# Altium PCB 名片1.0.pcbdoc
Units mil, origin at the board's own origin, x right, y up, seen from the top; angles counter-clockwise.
Board outline 3543.3 x 1925.99 mil, 2 copper layers (Top Layer, Bottom Layer); 29 components, 32 nets, 159 pads, 0 vias.
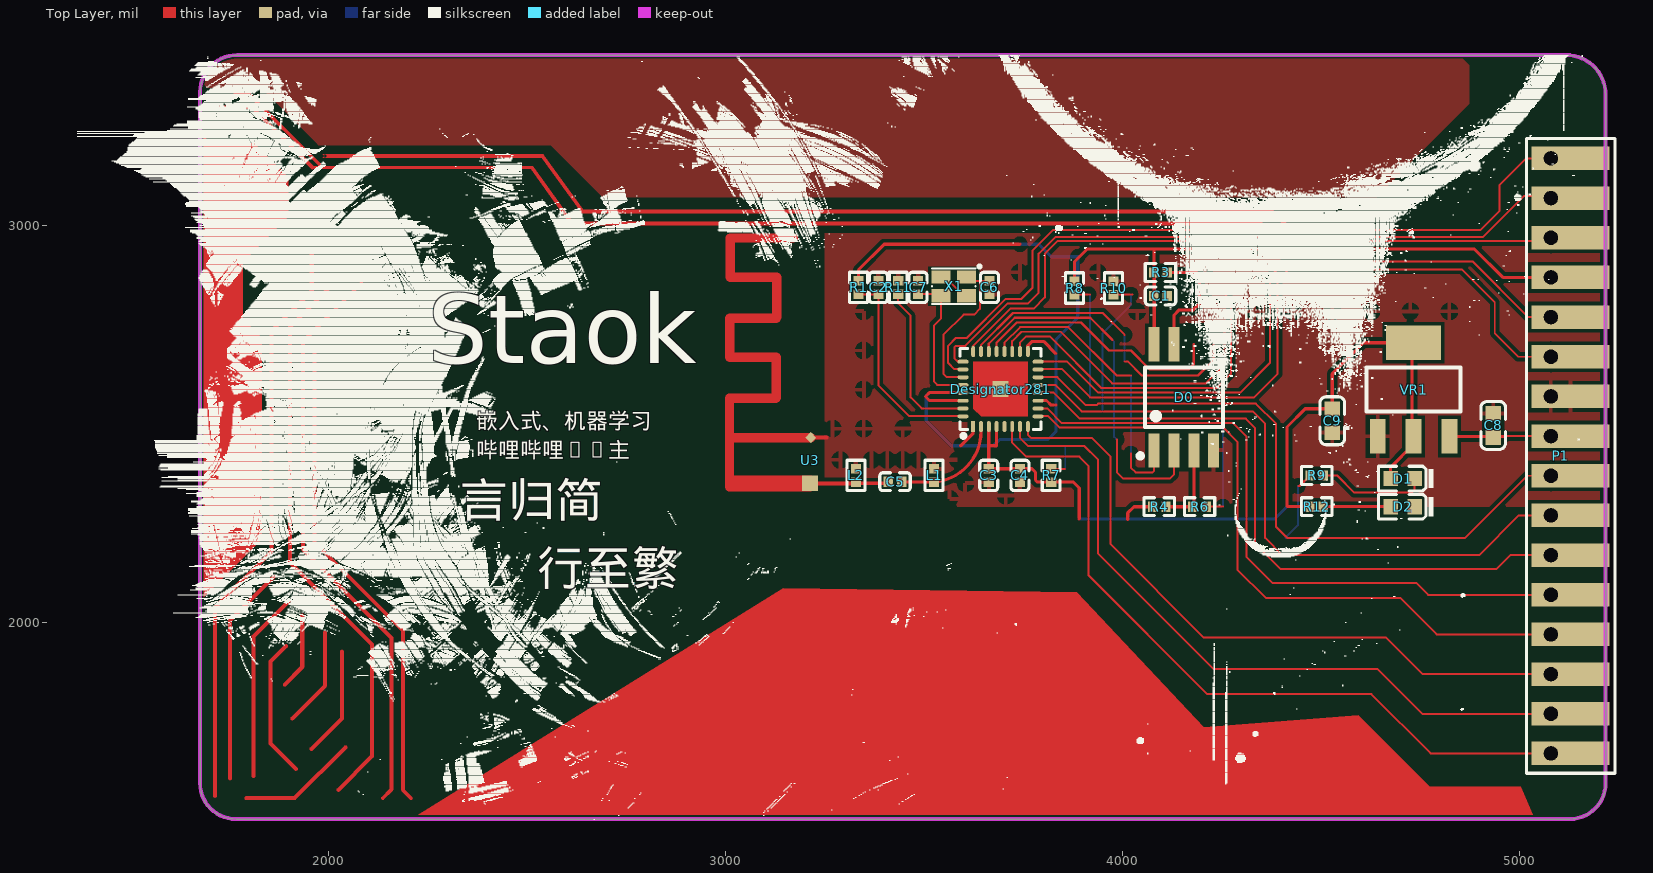
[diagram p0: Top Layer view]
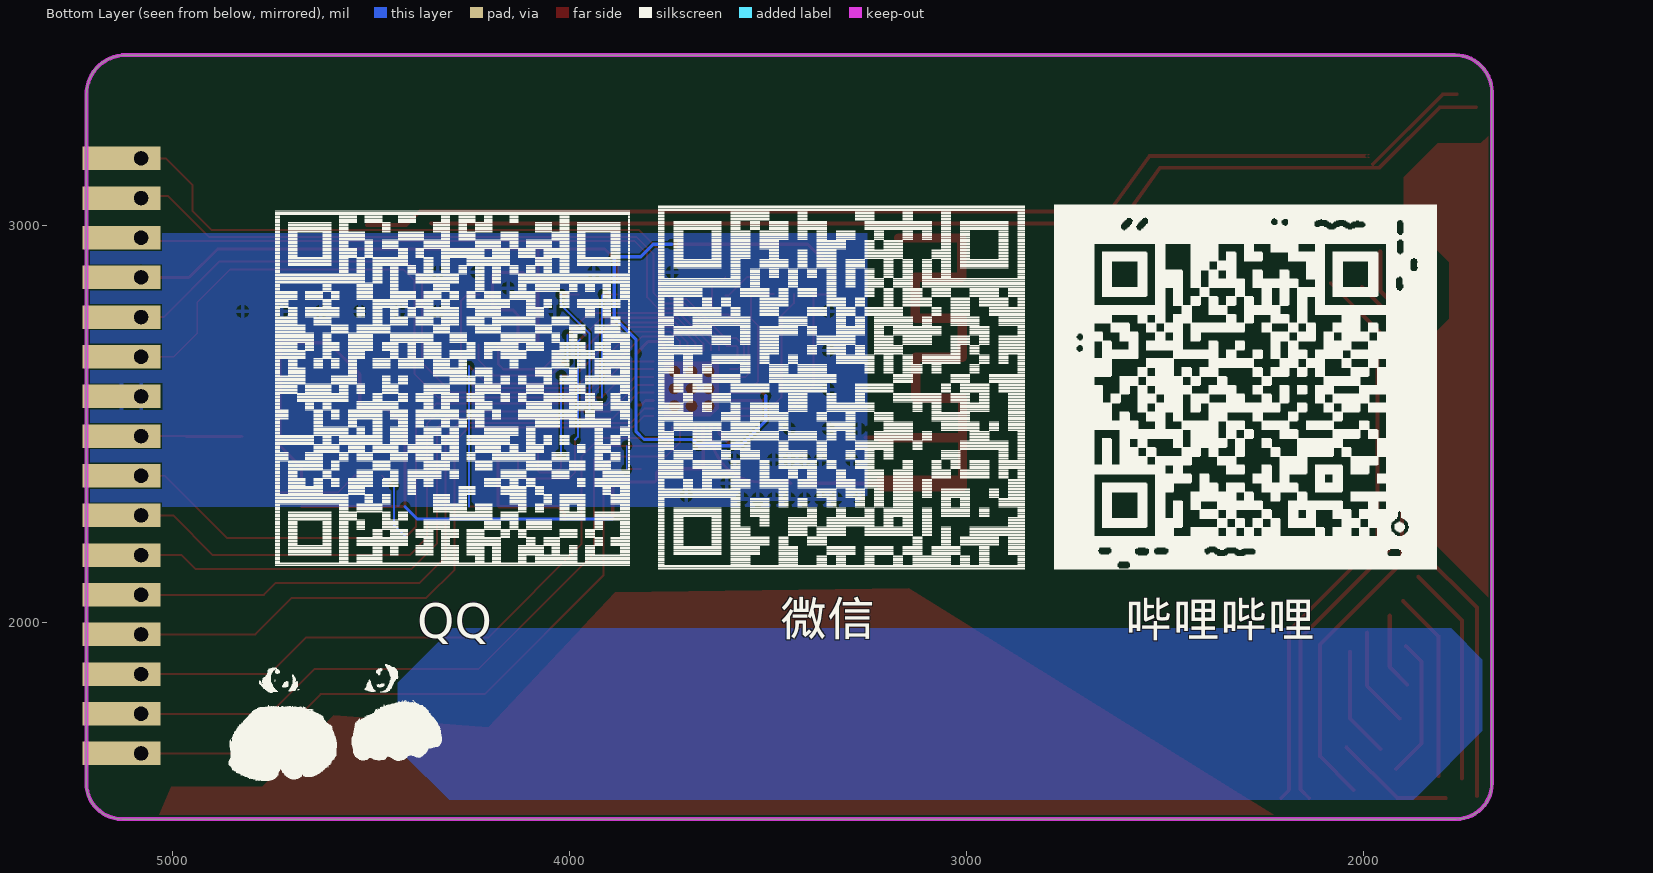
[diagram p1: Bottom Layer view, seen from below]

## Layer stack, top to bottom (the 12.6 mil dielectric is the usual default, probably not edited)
Top Layer: signal copper 1.4
Dielectric: dielectric 12.6, FR-4, Dk 4.8
Bottom Layer: signal copper 1.4

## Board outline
1675.04,1595.33 ccw(c1765.37,1595.33) 1765.37,1505 5128.01,1505 ccw(c5128.01,1595.33) 5218.34,1595.33 5218.34,3331.41 ccw(c5118.76,3331.41) 5118.76,3430.99 1768.9,3430.99 ccw(c1768.9,3337.13) 1675.04,3337.13

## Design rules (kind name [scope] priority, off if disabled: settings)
Clearance [All] p1: gap=4
ComponentClearance [All] p1 off: gap=10 collisioncheckmode=3 verticalgap=10 showdistances=FALSE
PolygonConnect [All] p1: connectstyle=Relief reliefconductorwidth=10 reliefentries=4 polygonreliefangle="90 Angle"
RoutingVias [All] p1: holewidth=28 width=50 viastyle="Through Hole" minholewidth=5 minwidth=5 maxholewidth=500 maxwidth=500
SilkscreenOverComponentPads [All] p1: minsilkscreentomaskgap=10
SolderMaskExpansion [All] p1: expansion=4
Width [All] p1: maxlimit=500 minlimit=5 preferedwidth=10
26 further rules are at their usual default settings.

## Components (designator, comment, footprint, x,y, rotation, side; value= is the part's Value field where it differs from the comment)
C1 "0.1uF" 0402_C 4096.3,2823.9 r0 top
C2 "1uF" 0402_C 3385.04,2845 r270 top
C3 "0.1uF" 0402_C 3663.22,2371.14 r90 top
C4 "10uF" 0402_C 3741.96,2371.14 r90 top
C5 "5.6pF" 0402_C 3427,2355.4 r0 top
C6 "3.9pF" 0402_C 3665.04,2845 r90 top
C7 "3.9pF" 0402_C 3485.04,2845 r270 top
C8 "10uF (106) 10% 10V" 0603_C#1 4934.88,2497.13 r270 top
C9 "10uF (106) 10% 10V" 0603_C#2 4529.37,2508.94 r90 top
D0 "W25Q128" SOIC-8_208MIL 4155.35,2567.99 r0 top
D1 "红灯 0603" 0603_LED_S1#1 4706.53,2363.27 r180 top
D2 "红灯 0603" 0603_LED_S1#2 4706.53,2292.4 r180 top
Designator281 "Comment" "QFN32 5x5_L" 3693,2589 r0 top
L1 "NC" 0402_L 3525.43,2371.14 r90 top
L2 "NC" 0402_L 3328.58,2371.14 r90 top
P1 "Header 16" HDR1X15 5080.55,3170.36 r270 top
R1 "12K" 0402_R 3335.04,2845 r90 top
R3 "0R/NC" 0402_R 4096.3,2882.96 r180 top
R4 "0R/NC" 0402_R 4093.34,2292.4 r180 top
R6 "0R/NC" 0402_R 4194.72,2292.4 r0 top
R7 "12K" 0402_R 3820.7,2371.14 r270 top
R8 "12K" 0402_R 3879.76,2843.59 r90 top
R9 "1K" 0402_R 4490,2371.14 r0 top
R10 "12K" 0402_R 3978.19,2843.59 r90 top
R11 "12K" 0402_R 3435.04,2845 r90 top
R12 "1K" 0402_R 4490,2292.4 r0 top
U3 "PCB_ANT" BLE-ANT4 3214.76,2466.42 r90 top
VR1 "AMS1117-3.3" SOT-223 4734.09,2587.68 r270 top
X1 "26MHz" SMT_XTAL_2520 3575.04,2845 r180 top

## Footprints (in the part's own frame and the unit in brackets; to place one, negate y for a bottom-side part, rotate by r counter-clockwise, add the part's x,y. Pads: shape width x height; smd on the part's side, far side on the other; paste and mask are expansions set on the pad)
0402_C [mm]
  rect 0.6x0.65 smd: 1(-0.425,0) 2(0.425,0)
  silkscreen extent -0.98,-0.58 0.97,0.58
0402_L [mm]
  rect 0.6x0.65 smd: 1(-0.425,0) 2(0.425,0)
  silkscreen extent -0.97,-0.58 0.98,0.58
0402_R [mm]
  rect 0.6x0.65 smd: 1(-0.425,0) 2(0.425,0)
  silkscreen extent -0.97,-0.57 0.98,0.58
0603_C#1 [mil]
  rect 36.61x38.58 smd: 1(-30.31,0) 2(30.32,0)
  silkscreen extent -60,-31 60,31
0603_C#2 [mil]
  rect 36.61x38.59 smd: 1(-30.32,0) 2(30.31,0)
  silkscreen extent -60,-31 60,31
0603_LED_S1#1 [mil]
  rect 36.61x38.58 smd: A(30.31,0) K(-30.32,0)
  silkscreen extent -78,-31 60,31
0603_LED_S1#2 [mil]
  rect 36.61x38.59 smd: A(30.31,0) K(-30.32,0)
  silkscreen extent -78,-31 60,31
BLE-ANT4 [mm]
  rect 0.5x0.5 smd rot 135: 1(0.005,0.005)
  rect 1x1 smd: 2(-2.923,0.052)
  Top Layer lines w0.6: 5.103,2.211 2.545,2.211 2.52,2.236 2.52,5.208 0.005,5.208 ; 5.136,2.211 5.136,5.183 7.65,5.183 7.65,2.211 ; 7.701,2.186 10.267,2.186 10.267,5.157 12.781,5.157 12.781,1.119 ; -3.145,0.052 -3.145,5.208 -2.738,5.208 ; -2.738,0.005 -2.738,0.052 -2.738,5.208 ; 0.005,0.005 0.005,5.208 ; -2.738,5.208 0.005,5.208
HDR1X15 [mm]
  rect 1.5x5 smd: 1(0,1.24) 2(2.54,1.24) 3(5.08,1.24) 4(7.62,1.24) 5(10.16,1.24) 6(12.7,1.24) 7(15.24,1.24) 8(17.78,1.24) 9(20.32,1.24) 10(22.86,1.24) 11(25.4,1.24) 12(27.94,1.24) 13(30.48,1.24) 14(33.02,1.24) 15(35.56,1.24) 16(38.1,1.24)
  rect 1.5x5 smd far side: 1(0,1.24) 2(2.54,1.24) 3(5.08,1.24) 4(7.62,1.24) 5(10.16,1.24) 6(12.7,1.24) 7(15.24,1.24) 8(17.78,1.24) 9(20.32,1.24) 10(22.86,1.24) 11(25.4,1.24) 12(27.94,1.24) 13(30.48,1.24) 14(33.02,1.24) 15(35.56,1.24) 16(38.1,1.24)
  round 1.5 hole 0.9 slot 0.9 at 0 deg: 1(0,0) 2(2.54,0) 3(5.08,0) 4(7.62,0) 5(10.16,0) 6(12.7,0) 7(15.24,0) 8(17.78,0) 9(20.32,0) 10(22.86,0) 11(25.4,0) 12(27.94,0) 13(30.48,0) 14(33.02,0) 15(35.56,0) 16(38.1,0)
  silkscreen extent -1.27,-1.57 39.37,4.1
"QFN32 5x5_L" [mm] "32脚，长x宽x"
  rect 0.25x0.7 smd: 1(-1.751,-2.4)
  oval 0.25x0.7 smd: 2(-1.25,-2.4) 3(-0.75,-2.4) 4(-0.25,-2.4) 5(0.25,-2.4) 6(0.75,-2.4) 7(1.25,-2.4) 8(1.75,-2.4) 17(1.75,2.4) 18(1.25,2.4) 19(0.75,2.4) 20(0.25,2.4) 21(-0.25,2.4) 22(-0.75,2.4) 23(-1.25,2.4) 24(-1.75,2.4)
  oval 0.7x0.25 smd: 9(2.4,-1.75) 10(2.4,-1.25) 11(2.4,-0.75) 12(2.4,-0.25) 13(2.4,0.25) 14(2.4,0.75) 15(2.4,1.25) 16(2.4,1.75) 25(-2.4,1.75) 26(-2.4,1.25) 27(-2.4,0.75) 28(-2.4,0.25) 29(-2.4,-0.25) 30(-2.4,-0.75) 31(-2.4,-1.25) 32(-2.4,-1.75)
  rect 1x1 smd: 33(0,0)
  Top Layer region: -1.75,1.75 1.75,1.75 1.75,-1.75 -1.25,-1.75 -1.75,-1.25
  silkscreen extent -2.6,-3.12 2.6,2.6, body extent -2.5,-2.5 2.5,2.5, height 0.93
SMT_XTAL_2520 [mil]
  rect 47.24x33.46 smd: 1(-31.98,-26.63) 2(31.99,-26.63) 3(31.99,20.62) 4(-31.98,20.62)
  silkscreen extent -69,-57 55,42
SOIC-8_208MIL [mil]
  rect 27.56x86.56 smd: 1(-75,-133.85) 2(-25,-133.85) 3(25,-133.85) 4(75,-133.85) 7(-25,133.86) 8(-75,133.86)
  rect 27.56x86.56 on Mech1: 5(75,133.86) 6(25,133.86)
  silkscreen extent -116,-153 98,75
SOT-223 [mm]
  rect 2.2x1 smd: 1(3,-2.3) 2(3,0) 3(3,2.3)
  rect 2.2x3.5 smd: 2(-3,0)
  silkscreen extent -1.4,-3 1.4,3

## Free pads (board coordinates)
  round 0 smd: 50(1854.76,2241.44) 51(1750.76,1884.5) 52(1809.76,1852.65) 53(1852.76,1781.04) 54(1932.76,1921.61) 55(1989.76,1849.74) 56(2032.76,1788.27) 57(1934.63,1578.59) 58(1901.76,2172.66) 59(1934.76,2186.42) 60(2057.68,2108.8) 63(1874.76,3256.42) 64(2964.76,3006.42) 65(3214.76,3036.42)

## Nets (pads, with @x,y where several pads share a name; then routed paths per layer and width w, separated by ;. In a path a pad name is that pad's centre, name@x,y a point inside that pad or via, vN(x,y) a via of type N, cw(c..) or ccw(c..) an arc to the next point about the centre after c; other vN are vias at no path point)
3V3: C1.1 C3.2 C4.2 C9.2 D0.8 D1.A P1.4 R1.2 R3.2 R4.2 R7.2 R8.2 R12.1 VR1.2 | length 5711.7
  Top Layer w7.87: 3592.36,2445.95 3623.85,2477.44 3623.85,2493.19 ; 3596.3,2560.12 3513.62,2560.12 3503.78,2569.96 3513.62,2579.81 3596.3,2579.81 ; 3663.22,2493.19 3663.22,2445.95 ; 3682.91,2493.19 3682.91,2445.95 3675.04,2445.95 3663.22,2445.95 ; 3761.65,2686.11 3761.65,2697.92 3772.83,2709.1 3801.65,2709.1 3832.52,2678.23 ; 3789.21,2560.12 3808.89,2560.12 3820.7,2548.31 3832.52,2548.31 ; 3891.57,2260.91 3891.57,2339.65 3876.81,2354.41 R7.2 3786.26,2354.41 3781.33,2359.33 3781.33,2379.02 3772.48,2387.88 C4.2 C3.2 3663.22,2445.95 ; R12.1 4415.19,2292.4 4415.19,2493.19 4461.26,2539.25 C9.2
  Top Layer w8: R1.2 3335.04,2889.41 3399.45,2953.82 3741.96,2953.82 ; R8.2 3879.76,2910.51 3911.26,2942.01 4887.63,2942.01 4959.29,2870.36 P1.4@5129.37,2870.36 ; 4013.62,2260.91 4013.62,2276.66 4029.37,2292.4 R4.2 ; R3.2 4079.56,2941.03 4080.55,2942.01 ; D0.8 R3.2@4080.35,2882.96 ; C9.2 4529.37,2627.05 4608.11,2705.79 4730.15,2705.79 VR1.2@4730.15,2469.57 ; D1.A 4676.22,2392.01 4734.09,2449.88 VR1.2@4734.09,2469.57
  Bottom Layer w7.87: 3505.74,2571.93 3505.74,2508.94 3568.74,2445.95 3592.36,2445.95 3675.04,2445.95 3690.78,2461.7 3812.83,2461.7 3832.52,2481.38 3832.52,2548.31 3832.52,2678.23 ; 3891.57,2260.91 4013.62,2260.91 4383.7,2260.91 4415.19,2292.4
  Bottom Layer w8: 3741.96,2953.82 3789.21,2953.82 3820.71,2922.33 3887.63,2922.33 3887.63,2768.78 3832.52,2713.66 3832.52,2678.23
5V: C8.2 P1.8 VR1.3 | length 444
  Top Layer w5: VR1.3 4825.43,2470.36 4967.16,2470.36 5080.55,2470.36 P1.8@5129.37,2470.36
  Top Layer w8: VR1.3@4828.58,2469.57 4966.37,2469.57 4967.16,2470.36
ADC: P1.16 | length 1932.6
  Top Layer w5: 3722.28,2493.19 3722.28,2453.82 3757.71,2418.39 3891.57,2418.39 3915.19,2394.77 3915.19,2118.9 4214.13,1819.96 4627.79,1819.96 4777.4,1670.36 5080.55,1670.36 P1.16@5129.37,1670.36
CLK:  | length 642.3
  Top Layer w6: 3682.91,2686.11 3682.91,2705.79 3733.9,2756.78 3895.7,2756.78 3966.37,2686.11 4021.49,2686.11 4068.74,2638.86 4167.16,2638.86 4180.35,2652.05 4180.35,2701.85
CS: D0.1 | length 754.3
  Top Layer w5: 3702.59,2686.11 3702.59,2705.6 3742.16,2745.16 3864.01,2745.16 3986.06,2623.11 4021.49,2623.11 ; 4021.49,2426.26 4021.49,2390.83 4033.3,2379.02 4076.61,2379.02 4080.35,2382.76 D0.1
  Bottom Layer w5: 4021.49,2426.26 4021.49,2623.11
D0: D0.2 | length 933.1
  Top Layer w5: 3986.06,2461.7 3986.06,2379.02 4001.81,2363.27 4119.92,2363.27 4130.35,2373.7 D0.2
  Top Layer w6: 3663.22,2686.11 3663.22,2703.07 3728.93,2768.78 3919.13,2768.78 3974.25,2713.66
  Bottom Layer w5: 3974.25,2713.66 3979.53,2708.38 3979.53,2468.23 3986.06,2461.7
D1:  | length 793.9
  Top Layer w5: 3643.54,2686.11 3643.54,2699.65 3724.48,2780.59 3950.63,2780.59 4005.74,2725.48 ; 4005.74,2658.55 4013.62,2658.55 4049.05,2623.11 4190.78,2623.11 4230.35,2662.68 4230.35,2701.85
  Bottom Layer w5: 4005.74,2658.55 4005.74,2725.48
EN: P1.15 R7.1 | length 1936.2
  Top Layer w5: 3741.97,2493.19 3741.97,2465.63 3761.65,2445.95 3856.14,2445.95 3903.38,2445.95 3938.82,2410.51 3938.82,2174.29 4230.15,1882.96 4643.54,1882.96 4756.14,1770.36 5080.55,1770.36 P1.15@5129.37,1770.36 ; R7.1 3855.15,2387.88 3856.14,2386.89
  Bottom Layer w5: 3856.14,2386.89 3856.14,2445.95
GND: C1.2 C2.1 C3.1 C4.1 C6.1 C7.1 C8.1 C9.1 D0.4 D2.K L1.2 L2.2 P1.7 R10.2 R11.2 U3.1 U3.2 VR1.1 X1.2 X1.4 | length 172.6
  Top Layer w5: X1.2 3552.51,2871.63 3599.75,2824.38 X1.4 ; P1.7@5080.55,2570.36 P1.7@5129.37,2570.36
  Top Layer w10: U3.1 3254.56,2466.62 3254.76,2466.42
IO0: P1.6 R8.1 | length 2082.1
  Top Layer w5: 3789.21,2638.86 3848.26,2638.86 3919.13,2567.99 4332.52,2567.99 4391.57,2627.05 4391.57,2863.27 4419.13,2890.83 4856.14,2890.83 4938.82,2808.15 4938.82,2729.41 4997.87,2670.36 5080.55,2670.36 P1.6@5129.37,2670.36 ; R8.1 3918.15,2826.85 3915.19,2827.84
  Bottom Layer w5: 3915.19,2827.84 3919.13,2823.9 3919.13,2567.99
IO2: P1.9 R9.1 | length 1913
  Top Layer w5: 3789.21,2619.18 3836.45,2619.18 3907.32,2548.31 3934.88,2548.31 3938.82,2552.25 4336.45,2552.25 4387.63,2501.07 4387.63,2241.22 4415.19,2213.66 4864.01,2213.66 5020.7,2370.36 5080.55,2370.36 P1.9@5129.37,2370.36 ; 4443.74,2344.57 4446.69,2344.57 R9.1
  Bottom Layer w5: 4411.26,2213.66 4442.75,2245.16 4442.75,2344.57
IO4: P1.5 | length 1694.8
  Top Layer w5: 3789.21,2658.55 3860.07,2658.55 3938.82,2579.81 4297.08,2579.81 4371.89,2654.61 4371.89,2871.42 4410.98,2910.51 4883.7,2910.51 5023.85,2770.36 5080.55,2770.36 P1.5@5129.37,2770.36
IO5: P1.3 | length 1694.8
  Top Layer w5: 3623.85,2686.11 3623.85,2697.92 3717.53,2791.59 3776.59,2791.59 3804.96,2819.96 3804.96,2930.2 3836.45,2961.7 5120.7,2961.7 P1.3@5129.37,2970.36
IO9:  | length 864
  Top Layer w5: 3741.97,2686.11 3741.97,2705.79 3757.71,2721.54 3816.77,2721.54 3946.69,2591.62 4238.03,2591.62 4273.46,2627.05 4273.46,2812.09 4257.71,2827.84 4227.2,2827.84
IO10: R6.2 | length 1033.3
  Top Layer w5: 3722.28,2686.11 3722.28,2709.73 3745.9,2733.35 3844.33,2733.35 3974.25,2603.43 4210.47,2603.43 4253.78,2646.74 ; R6.2 4253.78,2292.4
  Bottom Layer w5: 4253.78,2292.4 4253.78,2646.74
IO12: P1.12 | length 1712.5
  Top Layer w5: 3789.21,2540.44 3810.51,2540.44 3847.73,2503.22 4279.18,2503.22 4312.83,2469.57 4312.83,2166.42 4379.76,2099.49 4741.96,2099.49 4771.1,2070.36 5080.55,2070.36 P1.12@5129.37,2070.36
IO13: P1.11 | length 1709.8
  Top Layer w5: 3789.21,2579.81 3826.96,2579.81 3892.55,2514.22 4311.49,2514.22 4335.04,2490.67 4335.04,2199.33 4399.45,2134.92 4942.75,2134.92 4978.19,2170.36 5080.55,2170.36 P1.11@5129.37,2170.36
IO14: P1.13 | length 1756.7
  Top Layer w5: 3789.21,2520.75 3812.83,2520.75 3841.36,2492.22 4253.78,2492.22 4290.18,2455.81 4290.18,2133.95 4361.65,2062.48 4700.23,2062.48 4792.36,1970.36 5080.55,1970.36 P1.13@5129.37,1970.36
IO15: P1.10 R10.1 | length 2099
  Top Layer w5: 3789.21,2599.49 3830.71,2599.49 3897.63,2532.56 3950.63,2532.56 4328.58,2532.56 4360.08,2501.07 4360.08,2213.66 4403.38,2170.36 4899.45,2170.36 4999.45,2270.36 5080.55,2270.36 P1.10@5129.37,2270.36 ; R10.1 4021.49,2826.85 4024.45,2826.85 4025.43,2827.84
  Bottom Layer w5: 3950.63,2532.56 3950.63,2729.41 4021.49,2800.28 4021.49,2826.85
IO16: P1.14 | length 1766.4
  Top Layer w5: 3761.65,2493.19 3761.65,2473.51 3769.52,2465.63 3923.07,2465.63 3970.31,2418.39 3970.31,2197.92 4205.74,1962.48 4664.8,1962.48 4756.93,1870.36 5080.55,1870.36 P1.14@5129.37,1870.36
NETC2_2: C2.2 R1.1 | length 510.2
  Top Layer w5: 3348.26,2826.85 C2.2@3385.04,2826.85 ; C2.2 C2.2@3385.04,2826.85 ; 3596.3,2520.75 3462.44,2520.75 3385.04,2598.15 C2.2@3385.04,2826.85
NETC5_1: C5.1 L2.1 | length 200.1
  Top Layer w7.87: L2.1@3331.53,2351.46 C5.1@3410.27,2351.46
  Top Layer w10: 3212.71,2351.33 3325.5,2351.33 L2.1 L2.1@3331.53,2351.46
NETC5_2: C5.2 L1.1 | length 285.3
  Top Layer w7.87: C5.2@3446.69,2354.41 L1.1 ccw(c3515.1,2482.85) 3643.54,2493.19
  Top Layer w10: C5.2@3443.74,2351.46 C5.2@3446.69,2354.41
NETC6_2: C6.2 X1.1 | length 400.9
  Top Layer w5: 3596.3,2619.18 3556.92,2619.18 3549.05,2627.05 3549.05,2725.48 3600.23,2776.66 3626.69,2776.66 3640.98,2790.94 3640.98,2861.73 ; X1.1 3616.92,2861.73 3640.98,2861.73 ; C6.2 3640.98,2861.73
NETC7_2: C7.2 X1.3 | length 358.1
  Top Layer w5: C7.2 3539.16,2828.27 X1.3 3543.05,2766.99 3525.43,2749.37 3525.43,2607.36 3533.3,2599.49 3596.3,2599.49
NETD0_3: D0.3 R4.1 R6.1 | length 210.6
  Top Layer w8: R4.1 R6.1 4180.35,2294.77 D0.3
NETD0_7: D0.7 R3.1 | length 301.7
  Top Layer w8: R3.1@4116.96,2882.96 4186.85,2882.96 4194.72,2875.08 4194.72,2804.22 4178.97,2788.47 4143.54,2788.47 4130.35,2775.28 D0.7
NETD1_K: D1.K R9.2 | length 279.6
  Top Layer w5: R9.2 4541.18,2371.14 4584.48,2327.84 4730.15,2327.84 4736.85,2334.53 D1.K
NETD2_A: D2.A R12.2 | length 169.5
  Top Layer w7.87: R12.2 D2.A
NETR11_1: R11.1 | length 414.6
  Top Layer w5: R11.1 3435.04,2805 3466.37,2773.66 3466.37,2567.99 3493.93,2540.44 3596.3,2540.44
RX: P1.2 | length 1821.3
  Top Layer w5: 3596.3,2658.55 3584.48,2658.55 3576.61,2666.42 3576.61,2693.98 3580.55,2697.92 3604.17,2697.92 3710.47,2804.22 3761.65,2804.22 3789.21,2831.77 3789.21,2930.01 3831.9,2972.7 4909.63,2972.7 5012.8,3075.87 5123.85,3075.87 P1.2@5129.37,3070.36
TX: P1.1 | length 1943.2
  Top Layer w5: 3596.3,2638.86 3576.61,2638.86 3560.86,2654.61 3560.86,2697.92 3580.55,2717.6 3608.3,2717.6 3706.72,2816.03 3745.9,2816.03 3773.46,2843.59 3773.46,2938.07 3824.64,2989.25 4902.77,2989.25 4950.63,3037.11 4950.63,3102.63 5018.36,3170.36 5080.55,3170.36 P1.1@5129.37,3170.36
pads on no net: D0.5 D0.6 Designator281.1 Designator281.2 Designator281.3 Designator281.4 Designator281.5 Designator281.6 Designator281.7 Designator281.8 Designator281.9 Designator281.10 Designator281.11 Designator281.12 Designator281.13 Designator281.14 Designator281.15 Designator281.16 Designator281.17 Designator281.18 Designator281.19 Designator281.20 Designator281.21 Designator281.22 Designator281.23 Designator281.24 Designator281.25 Designator281.26 Designator281.27 Designator281.28 Designator281.29 Designator281.30 Designator281.31 Designator281.32 Designator281.33

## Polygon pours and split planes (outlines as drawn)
no net on Top Layer "Top Layer-No Net" (solid, pour order 8): 1757,3433 1752,3433 ccw(c1752,3359) 1678,3359 1689,3348 1805,3348 1829,3348 1969,3208 1973,3204 2549,3204 2559,3204 2688,3075 2690,3073 4412,3073 4640,3073 4803,3236 4875,3308 4875,3401 4875,3405 4848,3432 4846,3430 4668,3430
GND on Top Layer "Top Layer-GND" (solid, pour order 2): 3249.84,2981.38 3249.84,2292.4 5218.34,2292.4 5218.34,2981.38
no net on Bottom Layer "Top Layer-No Net" (solid, pour order 10): 1699,1904 1699,1727 1862,1564 1873,1553 4265,1553 4304,1553 4419,1668 4434,1683 4434,1820 4434,1848 4358,1924 4296,1986 1786,1986 1778,1986 1699,1907
GND on Bottom Layer "Bottom Layer-GND" (solid, pour order 4): 3249.84,2981.38 5218.34,2981.38 5218.34,2292.4 3249.84,2292.4

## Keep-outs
Keep-Out Layer:
  lines w10: 1675.04,1595.33 ccw(c1765.37,1595.33) 1765.37,1505 ; 1675.04,3337.13 cw(c1768.9,3337.13) 1768.9,3430.99 ; 5118.76,3430.99 cw(c5118.76,3331.41) 5218.34,3331.41 ; 5128.01,1505 ccw(c5128.01,1595.33) 5218.34,1595.33

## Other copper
Top Layer:
  region: 1991.24,3172.42 1983.75,3172.42 1984.32,3172.46 1984.88,3172.58 1985.42,3172.78 1985.92,3173.05 1986.37,3173.4 1986.78,3173.8 1987.12,3174.26 1987.39,3174.76 1987.59,3175.29 1987.71,3175.85 1987.75,3176.42 1987.71,3176.99 1987.59,3177.55 1987.39,3178.08 1987.12,3178.58 1986.78,3179.04 1986.37,3179.44 1985.92,3179.78 1985.42,3180.06 1984.88,3180.26 1984.32,3180.38 1983.75,3180.42 2538.75,3180.42 2539.39,3180.37 2540,3180.22 2540.58,3179.98 2541.12,3179.64 2541.6,3179.23 2542.01,3178.74 2640.81,3040.42 4378.26,3040.42 4378.89,3040.37 4379.5,3040.22 4380.08,3039.98 4380.62,3039.66 4381.09,3039.25 4413.9,3006.44 4511.24,3006.44 4511.81,3006.4 4512.37,3006.28 4512.91,3006.08 4513.41,3005.8 4513.86,3005.46 4514.27,3005.06 4514.61,3004.6 4514.88,3004.1 4515.08,3003.57 4515.2,3003.01 4515.24,3002.44 4515.2,3001.87 4515.08,3001.31 4514.88,3000.78 4514.61,3000.28 4514.27,2999.82 4513.86,2999.42 4513.41,2999.07 4512.91,2998.8 4512.37,2998.6 4511.81,2998.48 4511.24,2998.44 4412.24,2998.44 4411.62,2998.49 4411.01,2998.64 4410.43,2998.88 4409.89,2999.2 4409.42,2999.61 4376.61,3032.42 2638.75,3032.42 2638.12,3032.47 2637.51,3032.62 2636.92,3032.86 2636.39,3033.2 2635.91,3033.61 2635.5,3034.09 2536.7,3172.42 1983.75,3172.42 1984.32,3172.46 1984.88,3172.58 1985.42,3172.78 1985.92,3173.05 1986.37,3173.4 1986.78,3173.8 1987.12,3174.26 1987.39,3174.76 1987.59,3175.29 1987.71,3175.85 1987.75,3176.42 1987.71,3176.99 1987.59,3177.55 1987.39,3178.08 1987.12,3178.58 1986.78,3179.04 1986.37,3179.44 1985.92,3179.78 1985.42,3180.06 1984.88,3180.26 1984.32,3180.38 1983.75,3180.42 1991.24,3180.42 1991.81,3180.38 1992.37,3180.26 1992.91,3180.06 1993.41,3179.78 1993.86,3179.44 1994.27,3179.04 1994.61,3178.58 1994.88,3178.08 1995.08,3177.55 1995.2,3176.99 1995.24,3176.42 1995.2,3175.85 1995.08,3175.29 1994.88,3174.76 1994.61,3174.26 1994.27,3173.8 1993.86,3173.4 1993.41,3173.05 1992.91,3172.78 1992.37,3172.58 1991.81,3172.46
  region: 1715.47,3303.44 1806.47,3303.44 1807.1,3303.39 1807.71,3303.24 1808.29,3303 1808.83,3302.68 1809.3,3302.27 1961.15,3150.42 2511.98,3150.42 2512.62,3150.37 2513.23,3150.22 2513.81,3149.98 2514.35,3149.64 2514.83,3149.23 2515.24,3148.74 2614.04,3010.42 4349.47,3010.42 4350.04,3010.38 4350.6,3010.26 4351.14,3010.06 4351.64,3009.78 4352.09,3009.44 4352.5,3009.04 4352.84,3008.58 4353.11,3008.08 4353.31,3007.55 4353.43,3006.99 4353.47,3006.42 4353.43,3005.85 4353.31,3005.29 4353.11,3004.76 4352.84,3004.26 4352.5,3003.8 4352.09,3003.4 4351.64,3003.05 4351.14,3002.78 4350.6,3002.58 4350.04,3002.46 4349.47,3002.42 2611.98,3002.42 2611.35,3002.47 2610.74,3002.62 2610.15,3002.86 2609.62,3003.2 2609.14,3003.61 2608.73,3004.09 2509.93,3142.42 1959.49,3142.42 1958.87,3142.47 1958.26,3142.62 1957.68,3142.86 1957.14,3143.18 1956.67,3143.59 1804.82,3295.44 1715.47,3295.44 1714.91,3295.48 1714.35,3295.6 1713.81,3295.8 1713.31,3296.07 1712.86,3296.42 1712.45,3296.82 1712.11,3297.28 1711.84,3297.78 1711.64,3298.31 1711.52,3298.87 1711.47,3299.44 1711.52,3300.01 1711.64,3300.57 1711.84,3301.1 1712.11,3301.6 1712.45,3302.06 1712.86,3302.46 1713.31,3302.8 1713.81,3303.08 1714.35,3303.28 1714.91,3303.4
  region: 1763.88,3336.3 1798.88,3336.3 1799.51,3336.25 1800.12,3336.1 1800.7,3335.86 1801.24,3335.54 1801.71,3335.13 1978.22,3158.62 1978.6,3158.19 1978.91,3157.71 1979.14,3157.19 1979.3,3156.64 1979.38,3156.07 1979.38,3155.51 1979.3,3154.94 1979.14,3154.39 1978.91,3153.87 1978.6,3153.39 1978.22,3152.96 1977.79,3152.59 1977.31,3152.28 1976.79,3152.04 1976.24,3151.88 1975.68,3151.8 1975.11,3151.8 1974.54,3151.88 1974,3152.04 1973.48,3152.28 1973,3152.59 1972.57,3152.96 1797.23,3328.3 1763.88,3328.3 1763.32,3328.34 1762.76,3328.46 1762.22,3328.66 1761.72,3328.93 1761.27,3329.28 1760.86,3329.68 1760.52,3330.14 1760.25,3330.64 1760.05,3331.17 1759.93,3331.73 1759.88,3332.3 1759.93,3332.87 1760.05,3333.43 1760.25,3333.96 1760.52,3334.46 1760.86,3334.92 1761.27,3335.32 1761.72,3335.66 1762.22,3335.94 1762.76,3336.14 1763.32,3336.26
  region: 1967.76,2682.72 1967.76,2204.38 2189.59,1982.55 2190,1982.07 2190.33,1981.54 2190.57,1980.96 2190.72,1980.35 2190.76,1979.72 2190.76,1579.38 2209.59,1560.55 2209.97,1560.12 2210.28,1559.64 2210.51,1559.12 2210.67,1558.57 2210.75,1558.01 2210.75,1557.43 2210.67,1556.87 2210.51,1556.32 2210.28,1555.8 2209.97,1555.32 2209.59,1554.89 2209.16,1554.52 2208.68,1554.21 2208.16,1553.97 2207.61,1553.81 2207.05,1553.73 2206.48,1553.73 2205.91,1553.81 2205.37,1553.97 2204.85,1554.21 2204.37,1554.52 2203.94,1554.89 2183.94,1574.89 2183.53,1575.37 2183.2,1575.9 2182.96,1576.48 2182.81,1577.09 2182.76,1577.72 2182.76,1978.06 1960.94,2199.89 1960.53,2200.37 1960.2,2200.9 1959.96,2201.48 1959.81,2202.09 1959.76,2202.72 1959.76,2682.72 1959.81,2683.29 1959.93,2683.85 1960.13,2684.38 1960.4,2684.88 1960.74,2685.34 1961.15,2685.74 1961.6,2686.09 1962.1,2686.36 1962.64,2686.56 1963.2,2686.68 1963.76,2686.72 1964.33,2686.68 1964.89,2686.56 1965.43,2686.36 1965.93,2686.09 1966.38,2685.74 1966.79,2685.34 1967.13,2684.88 1967.4,2684.38 1967.6,2683.85 1967.72,2683.29
  region: 2084.59,2852.89 1938.76,2707.06 1938.76,2186.38 2160.59,1964.55 2161,1964.07 2161.33,1963.54 2161.57,1962.96 2161.72,1962.35 2161.76,1961.72 2161.76,1579.72 2161.72,1579.09 2161.57,1578.48 2161.33,1577.9 2161,1577.37 2160.59,1576.89 2138.59,1554.89 2138.16,1554.52 2137.68,1554.21 2137.16,1553.97 2136.61,1553.81 2136.05,1553.73 2135.48,1553.73 2134.91,1553.81 2134.37,1553.97 2133.85,1554.21 2133.37,1554.52 2132.94,1554.89 2132.56,1555.32 2132.25,1555.8 2132.02,1556.32 2131.86,1556.87 2131.77,1557.43 2131.77,1558.01 2131.86,1558.57 2132.02,1559.12 2132.25,1559.64 2132.56,1560.12 2132.94,1560.55 2153.76,1581.38 2153.76,1960.06 1931.94,2181.89 1931.53,2182.37 1931.2,2182.9 1930.96,2183.48 1930.81,2184.09 1930.76,2184.72 1930.76,2708.72 1930.81,2709.35 1930.96,2709.96 1931.2,2710.54 1931.53,2711.07 1931.94,2711.55 2078.94,2858.55 2079.37,2858.92 2079.85,2859.23 2080.37,2859.47 2080.91,2859.63 2081.48,2859.71 2082.05,2859.71 2082.61,2859.63 2083.16,2859.47 2083.68,2859.23 2084.16,2858.92 2084.59,2858.55 2084.97,2858.12 2085.28,2857.64 2085.51,2857.12 2085.67,2856.57 2085.75,2856.01 2085.75,2855.43 2085.67,2854.87 2085.51,2854.32 2085.28,2853.8 2084.97,2853.32
  region: 2005.95,2842.54 1906.26,2742.86 1906.26,2153.58 2111.95,1947.9 2112.41,1947.37 2112.77,1946.76 2113.04,1946.11 2113.21,1945.42 2113.26,1944.72 2113.26,1663.72 2113.21,1663.02 2113.04,1662.33 2112.77,1661.68 2112.41,1661.08 2111.95,1660.54 2026.95,1575.54 2026.48,1575.13 2025.97,1574.8 2025.42,1574.53 2024.83,1574.35 2024.22,1574.24 2023.61,1574.22 2023,1574.29 2022.4,1574.43 2021.83,1574.66 2021.3,1574.96 2020.81,1575.33 2020.37,1575.76 2020,1576.25 2019.7,1576.79 2019.48,1577.36 2019.33,1577.95 2019.27,1578.57 2019.29,1579.18 2019.39,1579.79 2019.58,1580.37 2019.84,1580.92 2020.18,1581.44 2020.58,1581.9 2104.26,1665.58 2104.26,1942.86 1898.58,2148.54 1898.12,2149.07 1897.75,2149.68 1897.48,2150.33 1897.32,2151.02 1897.26,2151.72 1897.26,2744.72 1897.32,2745.42 1897.48,2746.11 1897.75,2746.76 1898.12,2747.36 1898.58,2747.9 1999.58,2848.9 2000.05,2849.31 2000.56,2849.64 2001.11,2849.91 2001.7,2850.09 2002.3,2850.2 2002.92,2850.22 2003.53,2850.16 2004.13,2850.01 2004.7,2849.78 2005.23,2849.48 2005.72,2849.11 2006.16,2848.68 2006.53,2848.19 2006.83,2847.65 2007.05,2847.08 2007.2,2846.49 2007.26,2845.87 2007.24,2845.26 2007.14,2844.66 2006.95,2844.07 2006.69,2843.51 2006.35,2843
  region: 1791.76,1562.22 1911.9,1562.22 2038.58,1688.9 2039.05,1689.31 2039.56,1689.64 2040.11,1689.91 2040.7,1690.09 2041.3,1690.2 2041.92,1690.22 2042.53,1690.15 2043.13,1690.01 2043.7,1689.78 2044.23,1689.48 2044.72,1689.11 2045.16,1688.68 2045.53,1688.19 2045.83,1687.65 2046.05,1687.08 2046.2,1686.48 2046.26,1685.87 2046.24,1685.26 2046.14,1684.65 2045.95,1684.07 2045.69,1683.52 2045.35,1683 2044.95,1682.54 1916.95,1554.54 1916.41,1554.08 1915.81,1553.71 1915.16,1553.44 1914.47,1553.28 1913.76,1553.22 1791.76,1553.22 1791.15,1553.26 1790.55,1553.39 1789.97,1553.59 1789.43,1553.88 1788.92,1554.23 1788.48,1554.65 1788.09,1555.12 1787.77,1555.65 1787.52,1556.21 1787.36,1556.8 1787.27,1557.41 1787.27,1558.03 1787.36,1558.64 1787.52,1559.23 1787.77,1559.79 1788.09,1560.32 1788.48,1560.79 1788.92,1561.21 1789.43,1561.57 1789.97,1561.85 1790.55,1562.05 1791.15,1562.18
  region: 1952.58,1684.9 2028.26,1760.58 2028.26,1926.72 2028.31,1927.33 2028.43,1927.93 2028.64,1928.51 2028.92,1929.06 2029.27,1929.56 2029.69,1930.01 2030.17,1930.4 2030.69,1930.71 2031.26,1930.96 2031.85,1931.13 2032.46,1931.21 2033.07,1931.21 2033.68,1931.13 2034.27,1930.96 2034.83,1930.71 2035.36,1930.4 2035.84,1930.01 2036.26,1929.56 2036.61,1929.06 2036.89,1928.51 2037.1,1927.93 2037.22,1927.33 2037.26,1926.72 2037.26,1758.72 2037.21,1758.02 2037.04,1757.33 2036.77,1756.68 2036.41,1756.08 2035.95,1755.54 1958.95,1678.54 1958.48,1678.13 1957.97,1677.8 1957.42,1677.53 1956.83,1677.35 1956.22,1677.24 1955.61,1677.22 1955,1677.29 1954.4,1677.43 1953.83,1677.66 1953.3,1677.96 1952.81,1678.33 1952.37,1678.76 1952,1679.25 1951.7,1679.79 1951.48,1680.36 1951.33,1680.95 1951.27,1681.57 1951.29,1682.18 1951.39,1682.79 1951.58,1683.37 1951.84,1683.92 1952.18,1684.44
  region: 1904.58,1761.9 1985.26,1842.58 1985.26,1974.72 1985.31,1975.33 1985.43,1975.93 1985.64,1976.51 1985.92,1977.06 1986.27,1977.56 1986.69,1978.01 1987.17,1978.4 1987.69,1978.71 1988.26,1978.96 1988.85,1979.13 1989.46,1979.21 1990.07,1979.21 1990.68,1979.13 1991.27,1978.96 1991.83,1978.71 1992.36,1978.4 1992.84,1978.01 1993.26,1977.56 1993.61,1977.06 1993.89,1976.51 1994.1,1975.93 1994.22,1975.33 1994.26,1974.72 1994.26,1840.72 1994.21,1840.02 1994.04,1839.33 1993.77,1838.68 1993.41,1838.08 1992.95,1837.54 1910.95,1755.54 1910.48,1755.13 1909.97,1754.8 1909.42,1754.53 1908.83,1754.35 1908.22,1754.24 1907.61,1754.22 1907,1754.29 1906.4,1754.43 1905.83,1754.66 1905.3,1754.96 1904.81,1755.33 1904.37,1755.76 1904,1756.25 1903.7,1756.79 1903.48,1757.36 1903.33,1757.95 1903.27,1758.57 1903.29,1759.18 1903.39,1759.79 1903.58,1760.37 1903.84,1760.92 1904.18,1761.44
  region: 1885.58,1846.9 1928.26,1889.58 1928.26,2017.72 1928.31,2018.33 1928.43,2018.93 1928.64,2019.51 1928.92,2020.06 1929.27,2020.56 1929.69,2021.01 1930.17,2021.4 1930.69,2021.71 1931.26,2021.96 1931.85,2022.13 1932.46,2022.21 1933.07,2022.21 1933.68,2022.13 1934.27,2021.96 1934.83,2021.71 1935.36,2021.4 1935.84,2021.01 1936.26,2020.56 1936.61,2020.06 1936.89,2019.51 1937.1,2018.93 1937.22,2018.33 1937.26,2017.72 1937.26,1887.72 1937.21,1887.02 1937.04,1886.33 1936.77,1885.68 1936.41,1885.08 1935.95,1884.54 1891.95,1840.54 1891.48,1840.13 1890.97,1839.8 1890.42,1839.53 1889.83,1839.35 1889.22,1839.24 1888.61,1839.22 1888,1839.29 1887.4,1839.43 1886.83,1839.66 1886.3,1839.96 1885.81,1840.33 1885.37,1840.76 1885,1841.25 1884.7,1841.79 1884.48,1842.36 1884.33,1842.95 1884.27,1843.57 1884.29,1844.18 1884.39,1844.79 1884.58,1845.37 1884.84,1845.92 1885.18,1846.44
  region: 1913.58,1628.54 1849.58,1692.54 1849.12,1693.08 1848.75,1693.68 1848.48,1694.33 1848.32,1695.02 1848.26,1695.72 1848.26,1901.72 1848.32,1902.42 1848.48,1903.11 1848.75,1903.76 1849.12,1904.37 1849.58,1904.9 1888.58,1943.9 1889.05,1944.31 1889.56,1944.64 1890.11,1944.91 1890.7,1945.09 1891.3,1945.2 1891.92,1945.22 1892.53,1945.15 1893.13,1945.01 1893.7,1944.78 1894.23,1944.48 1894.72,1944.11 1895.16,1943.68 1895.53,1943.19 1895.83,1942.65 1896.05,1942.08 1896.2,1941.48 1896.26,1940.87 1896.24,1940.26 1896.14,1939.65 1895.95,1939.07 1895.69,1938.52 1895.35,1938 1894.95,1937.54 1857.26,1899.86 1857.26,1697.58 1919.95,1634.9 1920.35,1634.44 1920.69,1633.92 1920.95,1633.37 1921.14,1632.79 1921.24,1632.18 1921.26,1631.57 1921.2,1630.95 1921.05,1630.36 1920.83,1629.79 1920.53,1629.25 1920.16,1628.76 1919.72,1628.33 1919.23,1627.96 1918.7,1627.66 1918.13,1627.43 1917.53,1627.29 1916.92,1627.22 1916.3,1627.24 1915.7,1627.35 1915.11,1627.53 1914.56,1627.8 1914.05,1628.13
  region: 1805.26,1613.72 1805.26,1965.72 1805.32,1966.42 1805.48,1967.11 1805.75,1967.76 1806.12,1968.37 1806.58,1968.9 1895.58,2057.9 1896.05,2058.31 1896.56,2058.64 1897.11,2058.91 1897.7,2059.09 1898.3,2059.2 1898.92,2059.22 1899.53,2059.16 1900.13,2059.01 1900.7,2058.78 1901.23,2058.48 1901.72,2058.11 1902.16,2057.68 1902.53,2057.19 1902.83,2056.65 1903.05,2056.08 1903.2,2055.49 1903.26,2054.87 1903.24,2054.26 1903.14,2053.66 1902.95,2053.07 1902.69,2052.51 1902.35,2052 1901.95,2051.54 1814.26,1963.86 1814.26,1613.72 1814.22,1613.11 1814.1,1612.51 1813.89,1611.93 1813.61,1611.38 1813.26,1610.88 1812.84,1610.43 1812.36,1610.04 1811.83,1609.72 1811.27,1609.48 1810.68,1609.31 1810.07,1609.23 1809.46,1609.23 1808.85,1609.31 1808.26,1609.48 1807.69,1609.72 1807.17,1610.04 1806.69,1610.43 1806.27,1610.88 1805.92,1611.38 1805.64,1611.93 1805.43,1612.51 1805.31,1613.11
  region: 1746.26,1607.72 1746.26,2005.72 1746.32,2006.42 1746.48,2007.11 1746.75,2007.76 1747.12,2008.37 1747.58,2008.9 1857.58,2118.9 1858.05,2119.31 1858.56,2119.64 1859.11,2119.91 1859.7,2120.09 1860.3,2120.2 1860.92,2120.22 1861.53,2120.16 1862.13,2120.01 1862.7,2119.78 1863.23,2119.48 1863.72,2119.11 1864.16,2118.68 1864.53,2118.19 1864.83,2117.65 1865.05,2117.08 1865.2,2116.49 1865.26,2115.87 1865.24,2115.26 1865.14,2114.66 1864.95,2114.07 1864.69,2113.51 1864.35,2113 1863.95,2112.54 1755.26,2003.86 1755.26,1607.72 1755.22,1607.11 1755.1,1606.51 1754.89,1605.93 1754.61,1605.38 1754.26,1604.88 1753.84,1604.43 1753.36,1604.04 1752.83,1603.72 1752.27,1603.48 1751.68,1603.31 1751.07,1603.23 1750.46,1603.23 1749.85,1603.31 1749.26,1603.48 1748.69,1603.72 1748.17,1604.04 1747.69,1604.43 1747.27,1604.88 1746.92,1605.38 1746.64,1605.93 1746.43,1606.51 1746.31,1607.11
  region: 1708.26,1563.72 1708.26,2037.72 1708.32,2038.42 1708.48,2039.11 1708.75,2039.76 1709.12,2040.37 1709.58,2040.9 1850.26,2181.58 1850.26,2734.72 1850.32,2735.42 1850.48,2736.11 1850.75,2736.76 1851.12,2737.36 1851.58,2737.9 1952.26,2838.58 1952.26,2935.72 1952.31,2936.33 1952.43,2936.93 1952.64,2937.51 1952.92,2938.06 1953.27,2938.56 1953.69,2939.01 1954.17,2939.4 1954.69,2939.72 1955.26,2939.96 1955.85,2940.13 1956.46,2940.21 1957.07,2940.21 1957.68,2940.13 1958.27,2939.96 1958.83,2939.72 1959.36,2939.4 1959.84,2939.01 1960.26,2938.56 1960.61,2938.06 1960.89,2937.51 1961.1,2936.93 1961.22,2936.33 1961.26,2935.72 1961.26,2836.72 1961.21,2836.02 1961.04,2835.33 1960.77,2834.68 1960.41,2834.07 1959.95,2833.54 1859.26,2732.86 1859.26,2179.72 1859.21,2179.02 1859.04,2178.33 1858.77,2177.68 1858.41,2177.07 1857.95,2176.54 1717.26,2035.86 1717.26,1563.72 1717.22,1563.11 1717.1,1562.51 1716.89,1561.93 1716.61,1561.38 1716.26,1560.88 1715.84,1560.43 1715.36,1560.04 1714.83,1559.72 1714.27,1559.48 1713.68,1559.31 1713.07,1559.23 1712.46,1559.23 1711.85,1559.31 1711.26,1559.48 1710.69,1559.72 1710.17,1560.04 1709.69,1560.43 1709.27,1560.88 1708.92,1561.38 1708.64,1561.93 1708.43,1562.51 1708.31,1563.11
  region: 1684.76,3226.42 1702.76,3208.42 1811.76,3208.42 1897.76,3122.42 1897.76,3023.42 1782.76,2908.42 1782.76,2766.42 1830.76,2718.42 1830.76,2210.42 1684.76,2064.42
  region: 2224.76,1516.42 3144.76,2086.42 3884.76,2076.42 4204.76,1736.42 4594.76,1766.42 4774.76,1586.42 5004.76,1586.42 5034.76,1516.42

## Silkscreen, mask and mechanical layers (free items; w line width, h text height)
Top Overlay:
  drawing of 15006 lines, arcs and shapes, not listed
  text "Staok" at 2249,2596 h300
  text "嵌入式、机器学习" at 2372,2475 h70
  text "哔哩哔哩UP主" at 2372,2402 h70
  text "言归简" at 2331.34,2238.03 h150
  text "行至繁" at 2523.55,2067.18 h150
Bottom Overlay:
  drawing of 10692 lines, arcs and shapes, not listed
  text "微信" at 3470,1938.8 h150
  text "哔哩哔哩" at 2599,1937 h150
  text "QQ" at 4383.94,1931.73 h150
Top Solder:
  drawing of 14 lines, arcs and shapes, not listed
Bottom Solder:
  lines w10: 1729,1795 1897,1795 1957,1735 2628,1735 2675,1782 ; 1772,1755 1894,1633 2631,1633 2753,1755 4213,1755 ; 2192,1767 2570,1767 2614,1811 3046,1811 ; 3168.5,1814.5 3197,1786 4297,1786
Document:
  lines w0.1: 3371.95,2566.99 3373.95,2568.99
